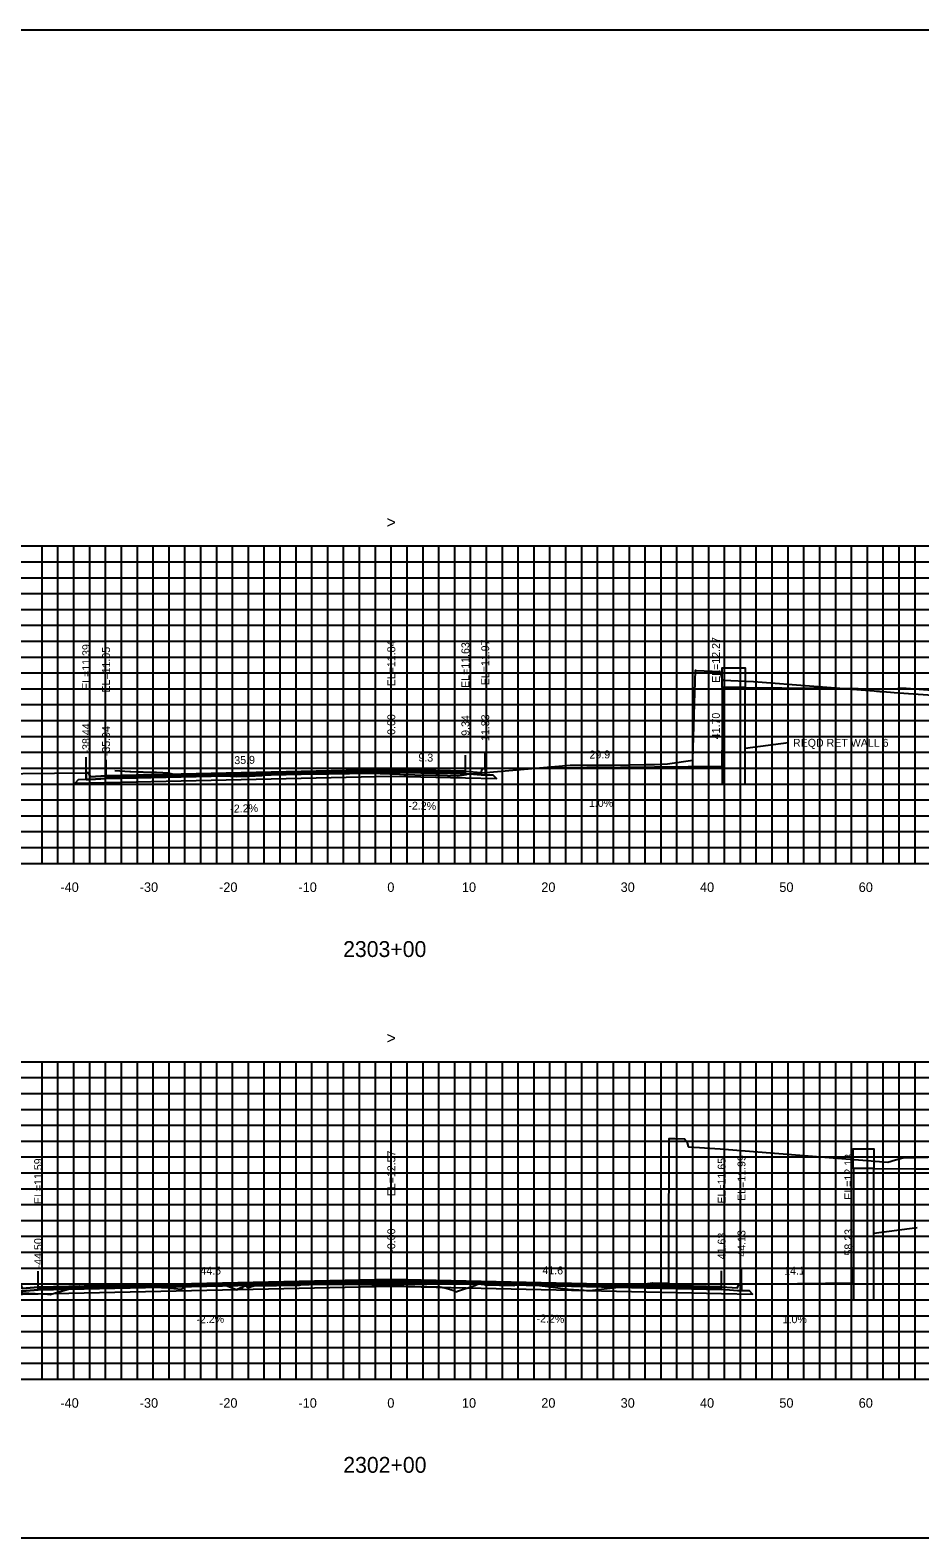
# Model space of a CAD drawing. Extents: x 1797682 to 1802785, y 249453 to 250269.
# Drawn here: x 1802585.5 to 1802697.6, y 250079.4 to 250269.4 of the extents above; entities that cross this region are included whole.
import ezdxf

# ---------------------------------------------------------------- set-up
doc = ezdxf.new("R2010")
doc.units = 0
for name, color, linetype in [('1', 7, 'Continuous'), ('10', 7, 'Continuous'), ('3', 7, 'Continuous'), ('4', 7, 'Continuous'), ('60', 7, 'Continuous'), ('BASE', 7, 'Continuous'), ('CL-CNST', 7, 'Continuous'), ('Level 62', 7, 'Continuous'), ('M-ROADS', 7, 'Continuous'), ('UPPER BINDER', 7, 'Continuous'), ('WEARING', 7, 'Continuous')]:
    doc.layers.add(name, color=color, linetype=linetype)

msp = doc.modelspace()

# ---------------------------------------------------------------- linework, layer by layer
for p, q in [((1802672.7, 250176.7), (1802672.7, 250178.7)), ((1802592.56, 250175.82), (1802592.56, 250177.82)), ((1802592.56, 250174.98), (1802592.56, 250176.98)), ((1802595.06, 250175.48), (1802595.06, 250177.48)), ((1802631, 250176.27), (1802631, 250178.27)), ((1802640.34, 250176.06), (1802640.34, 250178.06)), ((1802642.84, 250176.4), (1802642.84, 250178.4)), ((1802586.5, 250111.02), (1802586.5, 250113.02)), ((1802631, 250112), (1802631, 250114)), ((1802672.63, 250111.08), (1802672.63, 250113.08)), ((1802675.13, 250111.42), (1802675.13, 250113.42)), ((1802689.23, 250111.56), (1802689.23, 250113.56))]:
    msp.add_line(p, q)
for points in [[(1802481, 250079.43), (1802781, 250079.43), (1802781, 250269.43), (1802481, 250269.43)], [(1802595.06, 250175.48), (1802593.06, 250175.32), (1802592.89, 250175.82), (1802592.56, 250175.82), (1802592.56, 250174.98), (1802593.06, 250174.98), (1802595.06, 250175.14)], [(1802640.34, 250176.06), (1802642.34, 250175.9), (1802642.51, 250176.4), (1802642.84, 250176.4), (1802642.84, 250175.56), (1802642.34, 250175.56), (1802640.34, 250175.72)], [(1802586.5, 250111.02), (1802584.5, 250110.86), (1802584.33, 250111.36), (1802584, 250111.36), (1802584, 250110.52), (1802584.5, 250110.52), (1802586.5, 250110.68)], [(1802672.63, 250111.08), (1802674.63, 250110.92), (1802674.8, 250111.42), (1802675.13, 250111.42), (1802675.13, 250110.58), (1802674.63, 250110.58), (1802672.63, 250110.74)]]:
    msp.add_lwpolyline(points, close=True)
at = {"layer": '3'}
for p, q in [((1802681.07, 250179.62), (1802675.6, 250178.89)), ((1802697.28, 250118.51), (1802691.8, 250117.77))]:
    msp.add_line(p, q, dxfattribs=at)
at = {"layer": '60'}
for p, q in [((1802481, 250164.43), (1802781, 250164.43)), ((1802591, 250164.37), (1802591, 250164.43)), ((1802601, 250164.37), (1802601, 250164.43)), ((1802611, 250164.37), (1802611, 250164.43)), ((1802621, 250164.37), (1802621, 250164.43)), ((1802631, 250164.37), (1802631, 250164.43)), ((1802641, 250164.37), (1802641, 250164.43)), ((1802651, 250164.37), (1802651, 250164.43)), ((1802661, 250164.37), (1802661, 250164.43)), ((1802671, 250164.37), (1802671, 250164.43)), ((1802681, 250164.37), (1802681, 250164.43)), ((1802691, 250164.37), (1802691, 250164.43)), ((1802481, 250099.43), (1802781, 250099.43)), ((1802591, 250099.37), (1802591, 250099.43)), ((1802601, 250099.37), (1802601, 250099.43)), ((1802611, 250099.37), (1802611, 250099.43)), ((1802621, 250099.37), (1802621, 250099.43)), ((1802631, 250099.37), (1802631, 250099.43)), ((1802641, 250099.37), (1802641, 250099.43)), ((1802651, 250099.37), (1802651, 250099.43)), ((1802661, 250099.37), (1802661, 250099.43)), ((1802671, 250099.37), (1802671, 250099.43)), ((1802681, 250099.37), (1802681, 250099.43)), ((1802691, 250099.37), (1802691, 250099.43))]:
    msp.add_line(p, q, dxfattribs=at)
at = {"layer": 'BASE'}
for points in [[(1802640.34, 250175.22), (1802644.24, 250175.14), (1802643.84, 250175.54), (1802642.84, 250175.56), (1802642.34, 250175.56), (1802640.34, 250175.72), (1802640.34, 250175.72), (1802631, 250175.93), (1802595.06, 250175.14), (1802595.06, 250175.14), (1802593.06, 250174.98), (1802592.56, 250174.98), (1802591.56, 250174.96), (1802591.16, 250174.55), (1802595.06, 250174.64), (1802631, 250175.43)], [(1802672.63, 250110.24), (1802676.53, 250110.16), (1802676.13, 250110.56), (1802675.13, 250110.58), (1802674.63, 250110.58), (1802672.63, 250110.74), (1802672.63, 250110.74), (1802631, 250111.66), (1802586.5, 250110.68), (1802586.5, 250110.68), (1802584.5, 250110.52), (1802584, 250110.52), (1802583, 250110.5), (1802582.6, 250110.09), (1802586.5, 250110.18), (1802631, 250111.16)]]:
    msp.add_lwpolyline(points, close=True, dxfattribs=at)
at = {"layer": 'CL-CNST'}
for points in [[(1802675.6, 250186.59), (1802672.7, 250186.59), (1802672.7, 250189.09), (1802675.6, 250189.09)], [(1802672.7, 250174.43), (1802675.6, 250174.43), (1802675.6, 250186.59), (1802672.7, 250186.59)], [(1802691.8, 250125.97), (1802689.19, 250125.97), (1802689.19, 250128.47), (1802691.8, 250128.47)], [(1802689.23, 250109.43), (1802691.8, 250109.43), (1802691.8, 250125.97), (1802689.23, 250125.97)]]:
    msp.add_lwpolyline(points, close=True, dxfattribs=at)
for points in [[(1802675.6, 250186.59), (1802684.84, 250186.52), (1802694.82, 250186.44), (1802694.86, 250186.48), (1802694.89, 250186.51), (1802695.31, 250186.51), (1802695.89, 250186.51), (1802700.81, 250186.12), (1802707.9, 250185.57), (1802715.46, 250184.99), (1802719.91, 250184.64), (1802727.84, 250184.02), (1802731.92, 250183.71), (1802738.8, 250183.17), (1802741.93, 250182.93), (1802742.32, 250182.63), (1802743.19, 250181.96), (1802743.19, 250181.45), (1802743.19, 250181.23)], [(1802567.56, 250175.54), (1802572.56, 250175.62), (1802592.56, 250175.82), (1802592.89, 250175.82), (1802593.06, 250175.32), (1802595.06, 250175.48), (1802631, 250176.27), (1802640.34, 250176.06), (1802642.34, 250175.9), (1802642.51, 250176.4), (1802642.84, 250176.4), (1802672.7, 250176.7)], [(1802691.8, 250125.97), (1802696.88, 250125.94), (1802702.8, 250125.92), (1802702.83, 250125.95), (1802702.87, 250125.98), (1802703.44, 250125.98), (1802703.88, 250125.98), (1802711.17, 250125.44), (1802715.95, 250125.08), (1802720.29, 250124.75), (1802728.02, 250124.18), (1802731.75, 250123.9), (1802740.1, 250123.28), (1802742.7, 250123.08), (1802750.16, 250122.53), (1802750.44, 250122.31), (1802751.42, 250121.56), (1802751.42, 250120.99), (1802751.42, 250120.83)], [(1802575.86, 250111.18), (1802576, 250111.22), (1802577, 250111.26), (1802582, 250111.34), (1802584, 250111.36), (1802584.33, 250111.36), (1802584.5, 250110.86), (1802586.5, 250111.02), (1802631, 250112), (1802672.63, 250111.08), (1802674.63, 250110.92), (1802674.8, 250111.42), (1802675.13, 250111.42), (1802689.23, 250111.56)]]:
    msp.add_lwpolyline(points, dxfattribs=at)
at = {"layer": 'Level 62'}
for p, q in [((1802481, 250204.43), (1802781, 250204.43)), ((1802587, 250164.43), (1802587, 250204.43)), ((1802589, 250164.43), (1802589, 250204.43)), ((1802591, 250164.43), (1802591, 250204.43)), ((1802593, 250164.43), (1802593, 250204.43)), ((1802595, 250164.43), (1802595, 250204.43)), ((1802597, 250164.43), (1802597, 250204.43)), ((1802599, 250164.43), (1802599, 250204.43)), ((1802601, 250164.43), (1802601, 250204.43)), ((1802603, 250164.43), (1802603, 250204.43)), ((1802605, 250164.43), (1802605, 250204.43)), ((1802607, 250164.43), (1802607, 250204.43)), ((1802609, 250164.43), (1802609, 250204.43)), ((1802611, 250164.43), (1802611, 250204.43)), ((1802613, 250164.43), (1802613, 250204.43)), ((1802615, 250164.43), (1802615, 250204.43)), ((1802617, 250164.43), (1802617, 250204.43)), ((1802619, 250164.43), (1802619, 250204.43)), ((1802621, 250164.43), (1802621, 250204.43)), ((1802623, 250164.43), (1802623, 250204.43)), ((1802625, 250164.43), (1802625, 250204.43)), ((1802627, 250164.43), (1802627, 250204.43)), ((1802629, 250164.43), (1802629, 250204.43)), ((1802631, 250164.43), (1802631, 250204.43)), ((1802633, 250164.43), (1802633, 250204.43)), ((1802635, 250164.43), (1802635, 250204.43)), ((1802637, 250164.43), (1802637, 250204.43)), ((1802639, 250164.43), (1802639, 250204.43)), ((1802641, 250164.43), (1802641, 250204.43)), ((1802643, 250164.43), (1802643, 250204.43)), ((1802645, 250164.43), (1802645, 250204.43)), ((1802647, 250164.43), (1802647, 250204.43)), ((1802649, 250164.43), (1802649, 250204.43)), ((1802651, 250164.43), (1802651, 250204.43)), ((1802653, 250164.43), (1802653, 250204.43)), ((1802655, 250164.43), (1802655, 250204.43)), ((1802657, 250164.43), (1802657, 250204.43)), ((1802659, 250164.43), (1802659, 250204.43)), ((1802661, 250164.43), (1802661, 250204.43)), ((1802663, 250164.43), (1802663, 250204.43)), ((1802665, 250164.43), (1802665, 250204.43)), ((1802667, 250164.43), (1802667, 250204.43)), ((1802669, 250164.43), (1802669, 250204.43)), ((1802671, 250164.43), (1802671, 250204.43)), ((1802673, 250164.43), (1802673, 250204.43)), ((1802675, 250164.43), (1802675, 250204.43)), ((1802677, 250164.43), (1802677, 250204.43)), ((1802679, 250164.43), (1802679, 250204.43)), ((1802681, 250164.43), (1802681, 250204.43)), ((1802683, 250164.43), (1802683, 250204.43)), ((1802685, 250164.43), (1802685, 250204.43)), ((1802687, 250164.43), (1802687, 250204.43)), ((1802689, 250164.43), (1802689, 250204.43)), ((1802691, 250164.43), (1802691, 250204.43)), ((1802693, 250164.43), (1802693, 250204.43)), ((1802695, 250164.43), (1802695, 250204.43)), ((1802697, 250164.43), (1802697, 250204.43)), ((1802481, 250202.43), (1802781, 250202.43)), ((1802481, 250200.43), (1802781, 250200.43)), ((1802481, 250198.43), (1802781, 250198.43)), ((1802481, 250196.43), (1802781, 250196.43)), ((1802481, 250194.43), (1802781, 250194.43)), ((1802481, 250192.43), (1802781, 250192.43)), ((1802481, 250190.43), (1802781, 250190.43)), ((1802481, 250188.43), (1802781, 250188.43)), ((1802481, 250186.43), (1802781, 250186.43)), ((1802481, 250184.43), (1802781, 250184.43)), ((1802481, 250182.43), (1802781, 250182.43)), ((1802481, 250180.43), (1802781, 250180.43)), ((1802481, 250178.43), (1802781, 250178.43)), ((1802481, 250176.43), (1802781, 250176.43)), ((1802481, 250174.43), (1802781, 250174.43)), ((1802481, 250172.43), (1802781, 250172.43)), ((1802481, 250170.43), (1802781, 250170.43)), ((1802481, 250168.43), (1802781, 250168.43)), ((1802481, 250166.43), (1802781, 250166.43)), ((1802481, 250164.43), (1802781, 250164.43)), ((1802481, 250139.43), (1802781, 250139.43)), ((1802587, 250099.43), (1802587, 250139.43)), ((1802589, 250099.43), (1802589, 250139.43)), ((1802591, 250099.43), (1802591, 250139.43)), ((1802593, 250099.43), (1802593, 250139.43)), ((1802595, 250099.43), (1802595, 250139.43)), ((1802597, 250099.43), (1802597, 250139.43)), ((1802599, 250099.43), (1802599, 250139.43)), ((1802601, 250099.43), (1802601, 250139.43)), ((1802603, 250099.43), (1802603, 250139.43)), ((1802605, 250099.43), (1802605, 250139.43)), ((1802607, 250099.43), (1802607, 250139.43)), ((1802609, 250099.43), (1802609, 250139.43)), ((1802611, 250099.43), (1802611, 250139.43)), ((1802613, 250099.43), (1802613, 250139.43)), ((1802615, 250099.43), (1802615, 250139.43)), ((1802617, 250099.43), (1802617, 250139.43)), ((1802619, 250099.43), (1802619, 250139.43)), ((1802621, 250099.43), (1802621, 250139.43)), ((1802623, 250099.43), (1802623, 250139.43)), ((1802625, 250099.43), (1802625, 250139.43)), ((1802627, 250099.43), (1802627, 250139.43)), ((1802629, 250099.43), (1802629, 250139.43)), ((1802631, 250099.43), (1802631, 250139.43)), ((1802633, 250099.43), (1802633, 250139.43)), ((1802635, 250099.43), (1802635, 250139.43)), ((1802637, 250099.43), (1802637, 250139.43)), ((1802639, 250099.43), (1802639, 250139.43)), ((1802641, 250099.43), (1802641, 250139.43)), ((1802643, 250099.43), (1802643, 250139.43)), ((1802645, 250099.43), (1802645, 250139.43)), ((1802647, 250099.43), (1802647, 250139.43)), ((1802649, 250099.43), (1802649, 250139.43)), ((1802651, 250099.43), (1802651, 250139.43)), ((1802653, 250099.43), (1802653, 250139.43)), ((1802655, 250099.43), (1802655, 250139.43)), ((1802657, 250099.43), (1802657, 250139.43)), ((1802659, 250099.43), (1802659, 250139.43)), ((1802661, 250099.43), (1802661, 250139.43)), ((1802663, 250099.43), (1802663, 250139.43)), ((1802665, 250099.43), (1802665, 250139.43)), ((1802667, 250099.43), (1802667, 250139.43)), ((1802669, 250099.43), (1802669, 250139.43)), ((1802671, 250099.43), (1802671, 250139.43)), ((1802673, 250099.43), (1802673, 250139.43)), ((1802675, 250099.43), (1802675, 250139.43)), ((1802677, 250099.43), (1802677, 250139.43)), ((1802679, 250099.43), (1802679, 250139.43)), ((1802681, 250099.43), (1802681, 250139.43)), ((1802683, 250099.43), (1802683, 250139.43)), ((1802685, 250099.43), (1802685, 250139.43)), ((1802687, 250099.43), (1802687, 250139.43)), ((1802689, 250099.43), (1802689, 250139.43)), ((1802691, 250099.43), (1802691, 250139.43)), ((1802693, 250099.43), (1802693, 250139.43)), ((1802695, 250099.43), (1802695, 250139.43)), ((1802697, 250099.43), (1802697, 250139.43)), ((1802481, 250137.43), (1802781, 250137.43)), ((1802481, 250135.43), (1802781, 250135.43)), ((1802481, 250133.43), (1802781, 250133.43)), ((1802481, 250131.43), (1802781, 250131.43)), ((1802481, 250129.43), (1802781, 250129.43)), ((1802481, 250127.43), (1802781, 250127.43)), ((1802481, 250125.43), (1802781, 250125.43)), ((1802481, 250123.43), (1802781, 250123.43)), ((1802481, 250121.43), (1802781, 250121.43)), ((1802481, 250119.43), (1802781, 250119.43)), ((1802481, 250117.43), (1802781, 250117.43)), ((1802481, 250115.43), (1802781, 250115.43)), ((1802481, 250113.43), (1802781, 250113.43)), ((1802481, 250111.43), (1802781, 250111.43)), ((1802481, 250109.43), (1802781, 250109.43)), ((1802481, 250107.43), (1802781, 250107.43)), ((1802481, 250105.43), (1802781, 250105.43)), ((1802481, 250103.43), (1802781, 250103.43)), ((1802481, 250101.43), (1802781, 250101.43)), ((1802481, 250099.43), (1802781, 250099.43))]:
    msp.add_line(p, q, dxfattribs=at)
at = {"layer": 'M-ROADS'}
for points in [[(1802596.17, 250176.12), (1802597.41, 250176.04), (1802598.06, 250176.02), (1802598.18, 250176.02), (1802598.95, 250175.98), (1802599.62, 250175.95), (1802599.7, 250175.95), (1802599.82, 250175.94), (1802600.6, 250175.94), (1802601.28, 250175.94), (1802601.4, 250175.94), (1802602.2, 250175.87), (1802602.9, 250175.82), (1802603.01, 250175.81), (1802603.83, 250175.65), (1802604.55, 250175.59), (1802604.66, 250175.58), (1802605.5, 250175.6), (1802606.23, 250175.59), (1802606.35, 250175.59), (1802607.2, 250175.56), (1802607.95, 250175.55), (1802608.07, 250175.55), (1802609.71, 250175.49), (1802609.83, 250175.48), (1802610.72, 250175.44), (1802611.5, 250175.38), (1802612.86, 250175.41), (1802612.97, 250175.4), (1802613.04, 250175.4), (1802613.85, 250175.48), (1802614.57, 250175.52), (1802614.68, 250175.52), (1802615.52, 250175.68), (1802620.03, 250175.71), (1802620.67, 250175.72), (1802622, 250175.72), (1802622.08, 250175.72), (1802623.13, 250175.73), (1802628.39, 250175.79), (1802632.05, 250175.68), (1802632.1, 250175.67), (1802632.6, 250175.63), (1802633.12, 250175.62), (1802633.95, 250175.6), (1802636.62, 250175.54), (1802636.84, 250175.54), (1802639.35, 250175.46), (1802639.43, 250175.48), (1802640.45, 250175.65), (1802640.54, 250175.66), (1802653.53, 250176.79), (1802653.93, 250176.79), (1802654.09, 250176.79), (1802658.79, 250176.82), (1802663.07, 250176.89), (1802663.29, 250176.9), (1802664.06, 250176.91), (1802664.16, 250176.91), (1802665.81, 250176.96), (1802669.02, 250177.44), (1802669.02, 250177.52), (1802669.32, 250188.76), (1802669.44, 250188.75), (1802672.43, 250188.63), (1802672.68, 250187.55), (1802672.69, 250187.51), (1802672.73, 250187.51), (1802672.82, 250187.51), (1802676.66, 250187.34), (1802691.87, 250186.16), (1802692.14, 250186.14), (1802692.49, 250186.11), (1802692.62, 250186.1), (1802692.93, 250186.08), (1802694.38, 250185.98), (1802701.04, 250185.49)], [(1802577.48, 250110.69), (1802587.68, 250110.14), (1802587.75, 250110.13), (1802588, 250110.11), (1802588.58, 250110.28), (1802591.77, 250111.18), (1802602.06, 250110.97), (1802602.66, 250110.96), (1802603.11, 250110.91), (1802604.61, 250110.77), (1802605.34, 250111.26), (1802605.36, 250111.27), (1802605.77, 250111.27), (1802606.85, 250111.29), (1802607, 250111.29), (1802608.16, 250111.45), (1802608.27, 250111.45), (1802609.89, 250111.37), (1802611.24, 250110.83), (1802611.4, 250110.69), (1802612.03, 250110.96), (1802612.07, 250110.89), (1802612.07, 250110.89), (1802612.15, 250110.88), (1802612.25, 250110.89), (1802612.26, 250111.06), (1802612.73, 250111.25), (1802612.88, 250110.97), (1802612.88, 250110.97), (1802612.98, 250110.9), (1802613.03, 250110.9), (1802613.06, 250110.93), (1802613.06, 250110.93), (1802613.14, 250111.01), (1802613.15, 250111.01), (1802613.18, 250110.98), (1802613.21, 250111.01), (1802613.25, 250111.06), (1802613.68, 250111.19), (1802619.43, 250111.29), (1802619.78, 250111.36), (1802620.14, 250111.36), (1802620.65, 250111.35), (1802625.23, 250111.39), (1802625.44, 250111.39), (1802625.8, 250111.39), (1802635.32, 250111.11), (1802635.5, 250111.11), (1802636.17, 250111.08), (1802637.13, 250111.06), (1802637.23, 250111.04), (1802637.25, 250111.04), (1802637.27, 250111.04), (1802637.32, 250111.03), (1802637.41, 250111.01), (1802637.44, 250111), (1802637.74, 250110.94), (1802638.33, 250110.76), (1802638.87, 250110.59), (1802639.1, 250110.49), (1802639.26, 250110.44), (1802639.35, 250110.52), (1802641.52, 250111.25), (1802642.09, 250111.49), (1802642.35, 250111.5), (1802642.61, 250111.49), (1802642.81, 250111.31), (1802646.44, 250111.24), (1802646.72, 250111.41), (1802646.8, 250111.42), (1802647.25, 250111.45), (1802647.65, 250111.45), (1802647.67, 250111.45), (1802647.91, 250111.46), (1802648.21, 250111.41), (1802650.41, 250111.14), (1802653.29, 250110.77), (1802655.99, 250110.6), (1802658.97, 250110.92), (1802663.94, 250111.55), (1802665.71, 250111.51), (1802665.99, 250111.51), (1802665.99, 250115.93), (1802666, 250129.75), (1802666.72, 250129.75), (1802667.94, 250129.73), (1802668.15, 250129.46), (1802668.29, 250129.23), (1802668.41, 250128.73), (1802668.44, 250128.72), (1802669.84, 250128.61), (1802673.07, 250128.43), (1802673.5, 250128.39), (1802693.56, 250126.77), (1802694.55, 250127.06), (1802695.46, 250127.33), (1802698.6, 250127.4)]]:
    msp.add_lwpolyline(points, dxfattribs=at)
at = {"layer": 'UPPER BINDER'}
for points in [[(1802640.34, 250175.72), (1802640.34, 250175.91), (1802631, 250176.12), (1802595.06, 250175.33), (1802595.06, 250175.14), (1802631, 250175.93)], [(1802672.63, 250110.74), (1802672.63, 250110.93), (1802631, 250111.85), (1802586.5, 250110.87), (1802586.5, 250110.68), (1802631, 250111.66)]]:
    msp.add_lwpolyline(points, close=True, dxfattribs=at)
at = {"layer": 'WEARING'}
for points in [[(1802640.34, 250175.91), (1802640.34, 250176.06), (1802631, 250176.27), (1802595.06, 250175.48), (1802595.06, 250175.33), (1802631, 250176.12)], [(1802672.63, 250110.93), (1802672.63, 250111.08), (1802631, 250112), (1802586.5, 250111.02), (1802586.5, 250110.87), (1802631, 250111.85)]]:
    msp.add_lwpolyline(points, close=True, dxfattribs=at)

# ---------------------------------------------------------------- texts
at = {"layer": '1'}
for s, p in [('2303+00', (1802624.93, 250152.63)), ('2302+00', (1802624.95, 250087.63))]:
    msp.add_text(s, height=2, dxfattribs=at).set_placement(p)
at = {"layer": '10'}
for s, p in [('-40', (1802589.3, 250160.83)), ('-30', (1802599.3, 250160.83)), ('-20', (1802609.3, 250160.83)), ('-10', (1802619.3, 250160.83)), ('0', (1802630.5, 250160.83)), ('10', (1802639.9, 250160.83)), ('20', (1802649.9, 250160.83)), ('30', (1802659.9, 250160.83)), ('40', (1802669.9, 250160.83)), ('50', (1802679.9, 250160.83)), ('60', (1802689.9, 250160.83)), ('-40', (1802589.3, 250095.83)), ('-30', (1802599.3, 250095.83)), ('-20', (1802609.3, 250095.83)), ('-10', (1802619.3, 250095.83)), ('0', (1802630.5, 250095.83)), ('10', (1802639.9, 250095.83)), ('20', (1802649.9, 250095.83)), ('30', (1802659.9, 250095.83)), ('40', (1802669.9, 250095.83)), ('50', (1802679.9, 250095.83)), ('60', (1802689.9, 250095.83))]:
    msp.add_text(s, height=1.2, dxfattribs=at).set_placement(p)
at = {"layer": '3'}
for s, p in [('EL=11.84', (1802631.5, 250186.74)), ('EL=11.63', (1802640.84, 250186.54)), ('EL=11.97', (1802643.34, 250186.88)), ('EL=12.27', (1802672.41, 250187.18)), ('EL=11.39', (1802593.06, 250186.29)), ('EL=11.05', (1802595.56, 250185.95)), ('0.00', (1802631.5, 250180.63)), ('9.34', (1802640.84, 250180.5)), ('11.83', (1802643.34, 250179.85)), ('41.70', (1802672.41, 250180.07)), ('-38.44', (1802593.06, 250178.28)), ('-35.94', (1802595.56, 250177.94)), ('EL=12.57', (1802631.5, 250122.47)), ('EL=11.99', (1802675.63, 250121.89)), ('EL=12.13', (1802689.11, 250122.04)), ('EL=11.59', (1802587, 250121.49)), ('EL=11.65', (1802673.13, 250121.55)), ('-0.00', (1802631.5, 250115.37)), ('44.13', (1802675.63, 250114.87)), ('58.23', (1802689.11, 250115.01)), ('-44.50', (1802587, 250113.4)), ('41.63', (1802673.13, 250114.53))]:
    msp.add_text(s, height=1, rotation=90, dxfattribs=at).set_placement(p)
msp.add_text('REQD RET WALL 6', height=1, dxfattribs=at).set_placement((1802681.62, 250179.12))
at = {"layer": '4'}
for s, rotation, p in [('35.9', 1.2603, (1802611.23, 250176.93)), ('9.3', 358.7397, (1802634.41, 250177.29)), ('29.9', 0.5729, (1802655.98, 250177.64)), ('-2.2%', 1.2603, (1802610.73, 250170.82)), ('-2.2%', 358.7397, (1802633.15, 250171.22)), ('1.0%', 0.5729, (1802655.91, 250171.53)), ('44.5', 1.2603, (1802606.95, 250112.57)), ('41.6', 358.7397, (1802650.04, 250112.68)), ('14.1', 0.5729, (1802680.51, 250112.58)), ('-2.2%', 1.2603, (1802606.45, 250106.46)), ('-2.2%', 358.7397, (1802649.3, 250106.59)), ('1.0%', 0.5729, (1802680.32, 250106.47))]:
    msp.add_text(s, height=1, rotation=rotation, dxfattribs=at).set_placement(p)
at = {"layer": '60'}
for p in [(1802630.39, 250206.68), (1802630.39, 250141.68)]:
    msp.add_text('>', height=1.5, dxfattribs=at).set_placement(p)

doc.saveas('drawing.dxf')
